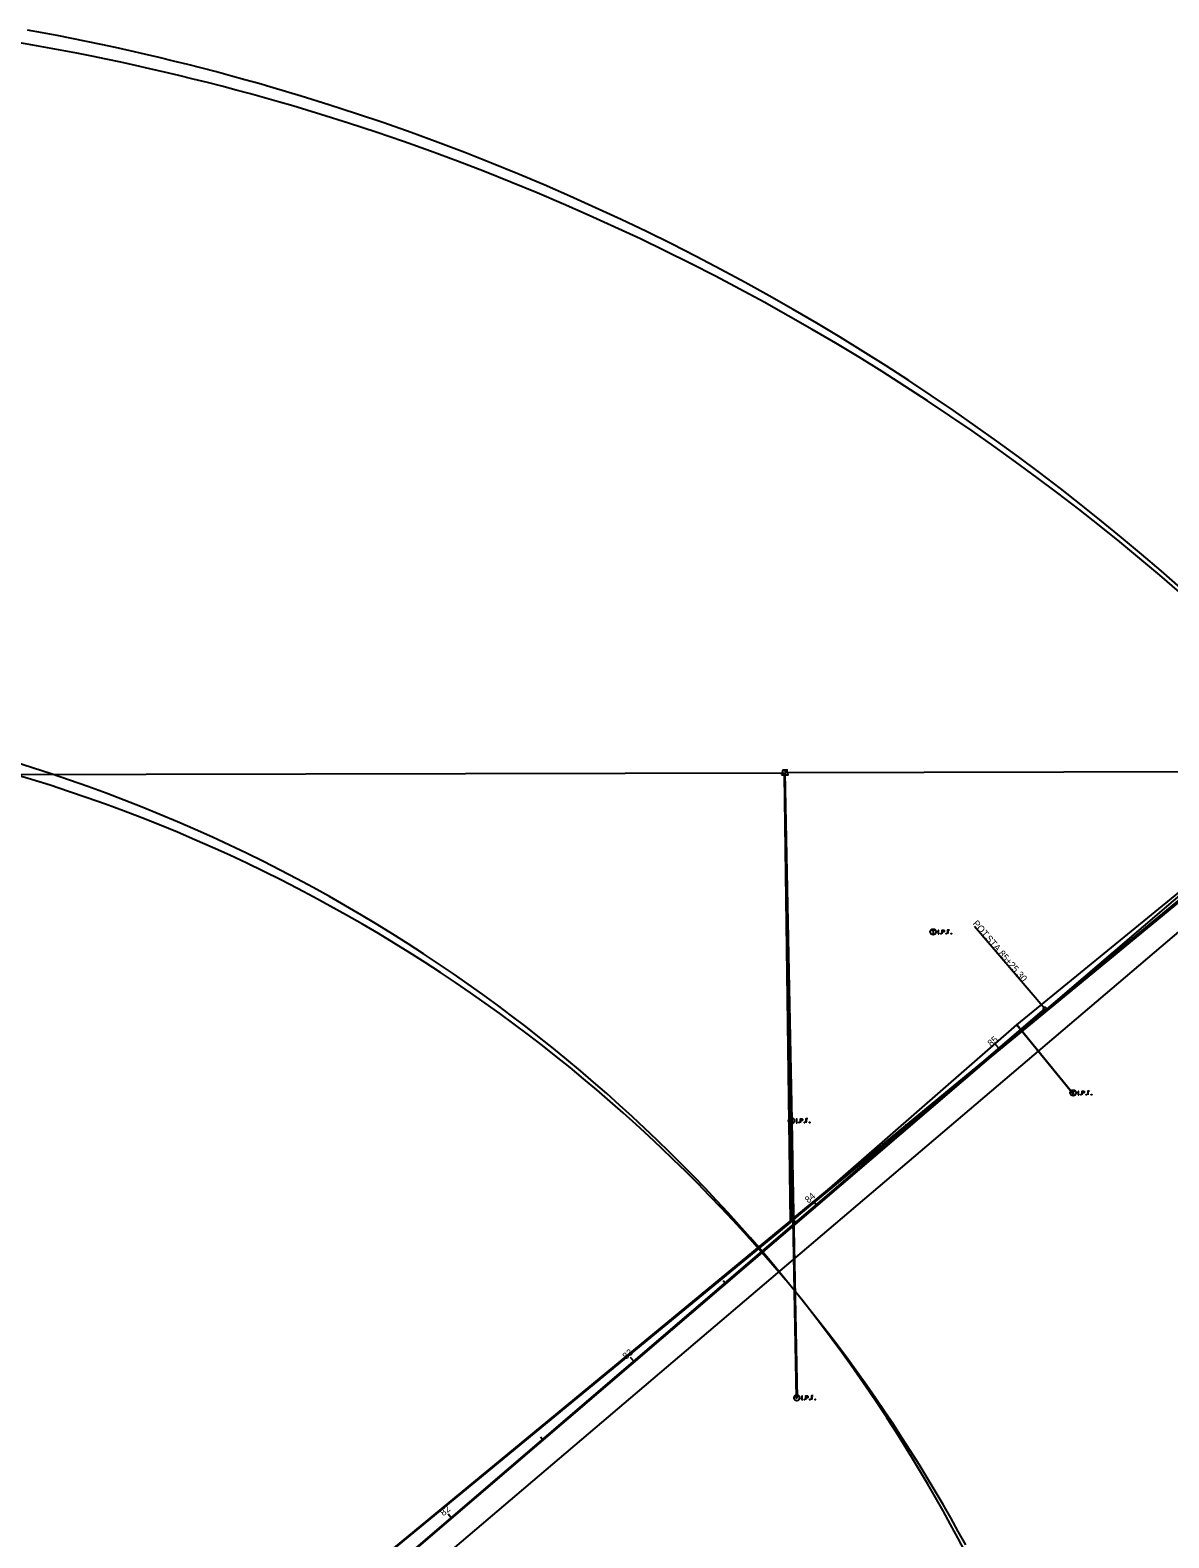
# Model space of a CAD drawing. Extents: x 2180160 to 2188891, y 366108 to 373879.
# Drawn here: x 2185585 to 2186059, y 370801 to 371428 of the extents above; entities that cross this region are included whole.
import ezdxf

# ---------------------------------------------------------------- set-up
doc = ezdxf.new("R2010")
doc.units = 0
for name, color, linetype in [('DR_Pond', 7, 'Continuous'), ('PV_X_Driveway', 7, 'Continuous'), ('RD_X_Concrete_Pad', 7, 'Continuous'), ('RD_X_Gate', 7, 'Continuous'), ('RW_P_Easement_Area', 7, 'Continuous'), ('RW_X_CL', 7, 'Continuous'), ('SC_Scratch1', 7, 'Continuous'), ('SC_Scratch4', 7, 'Continuous'), ('SC_Scratch5', 7, 'Continuous'), ('SC_Scratch6', 7, 'Continuous'), ('SC_Scratch8', 7, 'Continuous'), ('SV_P_Control_Cells_Set', 7, 'Continuous'), ('SV_X_Mon_Cells_Found', 7, 'Continuous'), ('SV_X_Shot_Marker', 7, 'Continuous')]:
    doc.layers.add(name, color=color, linetype=linetype)

msp = doc.modelspace()

# ---------------------------------------------------------------- linework, layer by layer
at = {"layer": 'DR_Pond'}
msp.add_line((2186007.46, 371021.34), (2185978.17, 371055.51), dxfattribs=at)
msp.add_circle((2186007.46, 371021.34), 0.6, dxfattribs=at)
at = {"layer": 'PV_X_Driveway'}
for p, q in [((2185988.25, 371004.87), (2185986.95, 371006.39)), ((2185950.29, 370972.33), (2185949.51, 370973.24)), ((2185912.33, 370939.78), (2185911.03, 370941.3)), ((2185874.37, 370907.24), (2185873.59, 370908.15)), ((2185836.41, 370874.7), (2185835.11, 370876.21)), ((2185798.46, 370842.15), (2185797.68, 370843.06)), ((2185760.5, 370809.61), (2185759.2, 370811.12))]:
    msp.add_line(p, q, dxfattribs=at)
at = {"layer": 'RD_X_Concrete_Pad'}
msp.add_line((2186829.27, 371121.5), (2185899.27, 371119.5), dxfattribs=at)
at = {"layer": 'RD_X_Gate'}
msp.add_line((2185899.28, 371119.5), (2185904.39, 370859.3), dxfattribs=at)
at = {"layer": 'RW_P_Easement_Area'}
msp.add_line((2185124.18, 370293.01), (2185902.93, 370933.53), dxfattribs=at)
at = {"layer": 'RW_X_CL'}
for q in [(2186007.46, 371021.34), (2185902.97, 370931.76)]:
    msp.add_line((2185380.91, 370484.16), q, dxfattribs=at)
at = {"layer": 'SC_Scratch1'}
for points in [[(2184931.61, 370719.54), (2184969.27, 371117.49), (2185899.27, 371119.5)], [(2185899.26, 371119.49), (2185902.12, 370974.78), (2185902.93, 370933.53), (2185124.18, 370293.01)]]:
    msp.add_lwpolyline(points, dxfattribs=at)
at = {"layer": 'SC_Scratch4'}
msp.add_lwpolyline([(2185898.94, 371118.61), (2185901.45, 370932.63), (2186129.11, 371120.01), (2185370.99, 370496.01), (2185380.69, 370483.98), (2185399.53, 370460.63), (2185361.86, 370507.33), (2185271.47, 370460.11), (2185108.08, 370328.3), (2185037.98, 370271.74), (2184997.75, 370213.58), (2184997.03, 370187.86), (2184952.11, 370150.89), (2184977.3, 370119.66), (2184958.46, 370143.01), (2184952.11, 370150.89), (2184426.3, 369718.09)], dxfattribs=at)
at = {"layer": 'SC_Scratch5'}
for p, q in [((2186133.45, 371128.46), (2185384.67, 370487.88)), ((2186140.76, 371119.43), (2185389.97, 370481.23)), ((2185899.28, 371119.5), (2185904.16, 370859.41))]:
    msp.add_line(p, q, dxfattribs=at)
for points in [[(2186063.88, 371196.36), (2186055.81, 371203.42), (2186047.64, 371210.41), (2186039.36, 371217.34), (2186030.98, 371224.2), (2186022.49, 371230.99), (2186013.9, 371237.71), (2186005.2, 371244.36), (2185996.4, 371250.93), (2185987.49, 371257.43), (2185978.48, 371263.85), (2185969.37, 371270.2), (2185960.15, 371276.46), (2185950.83, 371282.64), (2185941.41, 371288.73), (2185931.88, 371294.74), (2185922.26, 371300.65), (2185912.53, 371306.48), (2185902.7, 371312.21), (2185892.78, 371317.85), (2185882.75, 371323.4), (2185872.63, 371328.84), (2185862.41, 371334.18), (2185852.09, 371339.43), (2185841.68, 371344.56), (2185831.17, 371349.59), (2185820.57, 371354.52), (2185809.87, 371359.33), (2185799.09, 371364.03), (2185788.21, 371368.62), (2185777.24, 371373.09), (2185766.18, 371377.44), (2185755.03, 371381.67), (2185743.8, 371385.78), (2185732.48, 371389.77), (2185721.07, 371393.63), (2185709.58, 371397.36), (2185698.01, 371400.97), (2185686.36, 371404.44), (2185680.51, 371406.13), (2185674.63, 371407.78), (2185668.74, 371409.4), (2185662.82, 371410.98), (2185656.89, 371412.53), (2185650.94, 371414.05), (2185644.97, 371415.53), (2185638.98, 371416.98), (2185632.97, 371418.39), (2185626.95, 371419.76), (2185620.91, 371421.1), (2185614.85, 371422.41), (2185608.77, 371423.67), (2185602.67, 371424.9), (2185596.56, 371426.1), (2185590.43, 371427.26), (2185584.28, 371428.38)], [(2186063.36, 371194.64), (2186055.21, 371201.66), (2186046.96, 371208.61), (2186038.6, 371215.5), (2186030.13, 371222.32), (2186021.56, 371229.06), (2186012.88, 371235.74), (2186004.1, 371242.34), (2185995.21, 371248.87), (2185986.22, 371255.32), (2185977.13, 371261.69), (2185967.93, 371267.98), (2185958.63, 371274.19), (2185949.23, 371280.31), (2185939.72, 371286.35), (2185930.12, 371292.3), (2185920.41, 371298.16), (2185910.6, 371303.92), (2185900.69, 371309.59), (2185890.69, 371315.17), (2185880.58, 371320.64), (2185870.38, 371326.02), (2185860.08, 371331.29), (2185849.68, 371336.46), (2185839.19, 371341.53), (2185828.6, 371346.48), (2185817.92, 371351.33), (2185807.15, 371356.06), (2185796.28, 371360.69), (2185785.33, 371365.19), (2185774.28, 371369.58), (2185763.15, 371373.85), (2185751.93, 371377.99), (2185740.62, 371382.01), (2185729.23, 371385.91), (2185717.75, 371389.68), (2185706.19, 371393.32), (2185694.55, 371396.83), (2185688.7, 371398.54), (2185682.83, 371400.21), (2185676.94, 371401.84), (2185671.03, 371403.45), (2185665.11, 371405.02), (2185659.16, 371406.55), (2185653.19, 371408.05), (2185647.21, 371409.52), (2185641.21, 371410.95), (2185635.19, 371412.34), (2185629.15, 371413.7), (2185623.09, 371415.02), (2185617.02, 371416.31), (2185610.93, 371417.56), (2185604.82, 371418.77), (2185598.69, 371419.95), (2185592.55, 371421.09), (2185586.39, 371422.19), (2185580.22, 371423.26)], [(2185974.15, 370795.68), (2185971.2, 370801.27), (2185968.18, 370806.85), (2185965.1, 370812.42), (2185961.96, 370817.99), (2185958.75, 370823.54), (2185955.47, 370829.08), (2185952.12, 370834.62), (2185948.71, 370840.14), (2185945.24, 370845.64), (2185941.69, 370851.14), (2185938.08, 370856.62), (2185934.4, 370862.08), (2185930.65, 370867.53), (2185926.83, 370872.96), (2185922.95, 370878.37), (2185919, 370883.77), (2185914.97, 370889.14), (2185910.88, 370894.49), (2185906.72, 370899.82), (2185902.49, 370905.13), (2185898.18, 370910.41), (2185893.81, 370915.67), (2185889.37, 370920.9), (2185884.86, 370926.11), (2185880.27, 370931.29), (2185875.62, 370936.43), (2185870.89, 370941.55), (2185866.1, 370946.64), (2185861.23, 370951.69), (2185856.29, 370956.71), (2185851.28, 370961.7), (2185846.2, 370966.65), (2185841.05, 370971.56), (2185835.82, 370976.44), (2185830.53, 370981.28), (2185825.16, 370986.07), (2185819.72, 370990.83), (2185814.21, 370995.54), (2185808.63, 371000.21), (2185802.98, 371004.84), (2185797.26, 371009.41), (2185791.47, 371013.95), (2185785.61, 371018.43), (2185779.67, 371022.86), (2185773.67, 371027.24), (2185767.59, 371031.57), (2185761.45, 371035.85), (2185755.24, 371040.07), (2185748.95, 371044.23), (2185742.6, 371048.34), (2185736.18, 371052.39), (2185729.69, 371056.38), (2185723.14, 371060.3), (2185716.51, 371064.17), (2185709.82, 371067.97), (2185703.07, 371071.71), (2185696.24, 371075.38), (2185689.35, 371078.98), (2185682.4, 371082.51), (2185675.38, 371085.98), (2185668.29, 371089.37), (2185661.15, 371092.69), (2185653.94, 371095.93), (2185646.67, 371099.1), (2185639.33, 371102.19), (2185631.94, 371105.2), (2185624.48, 371108.14), (2185616.97, 371110.99), (2185609.39, 371113.76), (2185601.76, 371116.45), (2185594.07, 371119.05), (2185586.33, 371121.57), (2185578.53, 371124)], [(2185974.48, 370798.35), (2185971.42, 370803.93), (2185968.29, 370809.51), (2185965.1, 370815.07), (2185961.84, 370820.63), (2185958.51, 370826.17), (2185955.12, 370831.7), (2185951.66, 370837.22), (2185948.13, 370842.72), (2185944.54, 370848.22), (2185940.87, 370853.69), (2185937.14, 370859.15), (2185933.34, 370864.59), (2185929.48, 370870.02), (2185925.54, 370875.42), (2185921.53, 370880.81), (2185917.46, 370886.18), (2185913.31, 370891.52), (2185909.1, 370896.84), (2185904.81, 370902.14), (2185900.46, 370907.41), (2185896.03, 370912.65), (2185891.53, 370917.87), (2185886.97, 370923.07), (2185882.33, 370928.23), (2185877.62, 370933.36), (2185872.84, 370938.46), (2185867.99, 370943.53), (2185863.06, 370948.57), (2185858.07, 370953.57), (2185853, 370958.54), (2185847.87, 370963.47), (2185842.66, 370968.36), (2185837.38, 370973.22), (2185832.03, 370978.03), (2185826.6, 370982.8), (2185821.11, 370987.53), (2185815.55, 370992.22), (2185809.91, 370996.86), (2185804.2, 371001.46), (2185798.42, 371006.01), (2185792.57, 371010.51), (2185786.65, 371014.96), (2185780.66, 371019.36), (2185774.6, 371023.71), (2185768.47, 371028), (2185762.27, 371032.24), (2185756.01, 371036.43), (2185749.67, 371040.55), (2185743.26, 371044.62), (2185736.78, 371048.63), (2185730.24, 371052.58), (2185723.63, 371056.47), (2185716.95, 371060.29), (2185710.2, 371064.05), (2185703.39, 371067.74), (2185696.51, 371071.36), (2185689.57, 371074.92), (2185682.56, 371078.4), (2185675.49, 371081.82), (2185668.35, 371085.16), (2185661.15, 371088.42), (2185653.89, 371091.62), (2185646.57, 371094.73), (2185639.18, 371097.77), (2185631.73, 371100.73), (2185624.23, 371103.6), (2185616.67, 371106.4), (2185609.04, 371109.11), (2185601.36, 371111.74), (2185593.63, 371114.28), (2185585.84, 371116.73), (2185577.99, 371119.1)], [(2185899.27, 371119.5), (2185902, 370974.67), (2185902.77, 370933.42), (2185904.16, 370859.41), (2185902.77, 370933.42), (2185995.81, 371014.61), (2186019.17, 370986), (2185995.81, 371014.61), (2186127.45, 371122.17)]]:
    msp.add_lwpolyline(points, dxfattribs=at)
at = {"layer": 'SC_Scratch6'}
msp.add_lwpolyline([(2185899.27, 371119.5), (2185901.98, 370933.52), (2186129.44, 371121.15), (2185371.99, 370496.33), (2185381.71, 370484.31), (2185400.57, 370460.98), (2185371.99, 370496.33), (2184953.09, 370150.77), (2184427.75, 369717.42), (2184953.09, 370150.77), (2184959.46, 370142.91), (2184915.13, 370107.07), (2185381.71, 370484.31)], dxfattribs=at)
at = {"layer": 'SC_Scratch8'}
msp.add_lwpolyline([(2185898.94, 371118.61), (2185901.45, 370932.63), (2186129.11, 371120.01), (2185370.99, 370496.01), (2185380.69, 370483.98), (2185399.53, 370460.63), (2185361.86, 370507.33), (2185271.47, 370460.11), (2185108.08, 370328.3), (2185037.98, 370271.74), (2184997.75, 370213.58), (2184997.03, 370187.86), (2184952.11, 370150.89), (2184977.3, 370119.66), (2184958.46, 370143.01), (2184952.11, 370150.89), (2184863.14, 370077.66)], dxfattribs=at)
at = {"layer": 'SV_P_Control_Cells_Set'}
for p, q in [((2185902.27, 370932.86), (2185903.6, 370934.2)), ((2185902.27, 370934.2), (2185903.6, 370932.86))]:
    msp.add_line(p, q, dxfattribs=at)
at = {"layer": 'SV_X_Mon_Cells_Found'}
for p, q in [((2185899.27, 371120.59), (2185899.27, 371119.99)), ((2185960.96, 371053.37), (2185960.96, 371052.49)), ((2186019.21, 370986.41), (2186019.21, 370985.52)), ((2185901.99, 370974.85), (2185901.99, 370973.96))]:
    msp.add_line(p, q, dxfattribs=at)
msp.add_lwpolyline([(2185897.87, 371118.59), (2185900.67, 371118.59), (2185900.07, 371120.59), (2185898.47, 371120.59)], close=True, dxfattribs=at)
for points in [[(2185962.99, 371054.06), (2185963.34, 371054.06)], [(2185962.99, 371052.46), (2185963.34, 371052.46)], [(2185963.17, 371052.46), (2185963.17, 371054.06)], [(2185964.13, 371052.67), (2185964.18, 371052.67), (2185964.22, 371052.65), (2185964.25, 371052.6), (2185964.25, 371052.53), (2185964.22, 371052.48), (2185964.18, 371052.46), (2185964.13, 371052.46), (2185964.09, 371052.48), (2185964.06, 371052.53), (2185964.06, 371052.6), (2185964.09, 371052.65), (2185964.13, 371052.67)], [(2185964.73, 371052.46), (2185964.73, 371054.06), (2185965.26, 371054.06), (2185965.32, 371054.05), (2185965.39, 371054.02), (2185965.43, 371054), (2185965.46, 371053.97), (2185965.51, 371053.91), (2185965.54, 371053.84), (2185965.56, 371053.74), (2185965.56, 371053.59), (2185965.55, 371053.54), (2185965.53, 371053.47), (2185965.48, 371053.38), (2185965.44, 371053.34), (2185965.41, 371053.31), (2185965.35, 371053.29), (2185965.26, 371053.28), (2185964.73, 371053.28)], [(2185966.38, 371052.67), (2185966.43, 371052.67), (2185966.46, 371052.65), (2185966.5, 371052.6), (2185966.5, 371052.53), (2185966.46, 371052.48), (2185966.43, 371052.46), (2185966.38, 371052.46), (2185966.34, 371052.48), (2185966.31, 371052.53), (2185966.31, 371052.6), (2185966.34, 371052.65), (2185966.38, 371052.67)], [(2185967.74, 371054.06), (2185966.98, 371054.06), (2185966.98, 371052.46)], [(2185966.98, 371053.28), (2185967.52, 371053.28)], [(2185968.53, 371052.67), (2185968.58, 371052.67), (2185968.61, 371052.65), (2185968.65, 371052.6), (2185968.65, 371052.53), (2185968.61, 371052.48), (2185968.58, 371052.46), (2185968.53, 371052.46), (2185968.49, 371052.48), (2185968.46, 371052.53), (2185968.46, 371052.6), (2185968.49, 371052.65), (2185968.53, 371052.67)], [(2186021.24, 370987.09), (2186021.59, 370987.09)], [(2186021.42, 370985.49), (2186021.42, 370987.09)], [(2186022.98, 370985.49), (2186022.98, 370987.09), (2186023.51, 370987.09), (2186023.57, 370987.08), (2186023.64, 370987.05), (2186023.68, 370987.03), (2186023.71, 370987), (2186023.75, 370986.94), (2186023.79, 370986.88), (2186023.81, 370986.78), (2186023.81, 370986.62), (2186023.8, 370986.57), (2186023.77, 370986.5), (2186023.73, 370986.41), (2186023.69, 370986.37), (2186023.65, 370986.35), (2186023.6, 370986.32), (2186023.51, 370986.31), (2186022.98, 370986.31)], [(2186025.99, 370987.09), (2186025.23, 370987.09), (2186025.23, 370985.49)], [(2186025.23, 370986.31), (2186025.77, 370986.31)], [(2186021.24, 370985.49), (2186021.59, 370985.49)], [(2186022.37, 370985.7), (2186022.43, 370985.7), (2186022.46, 370985.68), (2186022.5, 370985.63), (2186022.5, 370985.57), (2186022.46, 370985.52), (2186022.43, 370985.49), (2186022.37, 370985.49), (2186022.34, 370985.52), (2186022.31, 370985.57), (2186022.31, 370985.63), (2186022.34, 370985.68), (2186022.37, 370985.7)], [(2186024.62, 370985.7), (2186024.68, 370985.7), (2186024.71, 370985.68), (2186024.74, 370985.63), (2186024.74, 370985.57), (2186024.71, 370985.52), (2186024.68, 370985.49), (2186024.62, 370985.49), (2186024.59, 370985.52), (2186024.56, 370985.57), (2186024.56, 370985.63), (2186024.59, 370985.68), (2186024.62, 370985.7)], [(2186026.77, 370985.7), (2186026.83, 370985.7), (2186026.86, 370985.68), (2186026.89, 370985.63), (2186026.89, 370985.57), (2186026.86, 370985.52), (2186026.83, 370985.49), (2186026.77, 370985.49), (2186026.74, 370985.52), (2186026.71, 370985.57), (2186026.71, 370985.63), (2186026.74, 370985.68), (2186026.77, 370985.7)], [(2185904.02, 370975.53), (2185904.38, 370975.53)], [(2185904.02, 370973.93), (2185904.38, 370973.93)], [(2185904.2, 370973.93), (2185904.2, 370975.53)], [(2185905.16, 370974.14), (2185905.21, 370974.14), (2185905.25, 370974.12), (2185905.28, 370974.07), (2185905.28, 370974.01), (2185905.25, 370973.96), (2185905.21, 370973.93), (2185905.16, 370973.93), (2185905.13, 370973.96), (2185905.09, 370974.01), (2185905.09, 370974.07), (2185905.13, 370974.12), (2185905.16, 370974.14)], [(2185905.77, 370973.93), (2185905.77, 370975.53), (2185906.3, 370975.53), (2185906.35, 370975.52), (2185906.43, 370975.49), (2185906.46, 370975.47), (2185906.49, 370975.44), (2185906.54, 370975.38), (2185906.57, 370975.32), (2185906.59, 370975.21), (2185906.59, 370975.06), (2185906.58, 370975.01), (2185906.56, 370974.94), (2185906.52, 370974.85), (2185906.47, 370974.81), (2185906.44, 370974.79), (2185906.38, 370974.76), (2185906.3, 370974.75), (2185905.77, 370974.75)], [(2185907.41, 370974.14), (2185907.46, 370974.14), (2185907.5, 370974.12), (2185907.53, 370974.07), (2185907.53, 370974.01), (2185907.5, 370973.96), (2185907.46, 370973.93), (2185907.41, 370973.93), (2185907.38, 370973.96), (2185907.34, 370974.01), (2185907.34, 370974.07), (2185907.38, 370974.12), (2185907.41, 370974.14)], [(2185908.78, 370975.53), (2185908.01, 370975.53), (2185908.01, 370973.93)], [(2185908.01, 370974.75), (2185908.55, 370974.75)], [(2185909.56, 370974.14), (2185909.61, 370974.14), (2185909.65, 370974.12), (2185909.68, 370974.07), (2185909.68, 370974.01), (2185909.65, 370973.96), (2185909.61, 370973.93), (2185909.56, 370973.93), (2185909.52, 370973.96), (2185909.49, 370974.01), (2185909.49, 370974.07), (2185909.52, 370974.12), (2185909.56, 370974.14)], [(2185906.31, 370860.27), (2185906.66, 370860.27)], [(2185906.31, 370858.67), (2185906.66, 370858.67)], [(2185906.49, 370858.67), (2185906.49, 370860.27)], [(2185907.44, 370858.89), (2185907.5, 370858.89), (2185907.53, 370858.86), (2185907.57, 370858.81), (2185907.57, 370858.75), (2185907.53, 370858.7), (2185907.5, 370858.67), (2185907.44, 370858.67), (2185907.41, 370858.7), (2185907.38, 370858.75), (2185907.38, 370858.81), (2185907.41, 370858.86), (2185907.44, 370858.89)], [(2185908.05, 370858.67), (2185908.05, 370860.27), (2185908.58, 370860.27), (2185908.63, 370860.26), (2185908.71, 370860.23), (2185908.74, 370860.21), (2185908.78, 370860.18), (2185908.82, 370860.12), (2185908.86, 370860.06), (2185908.88, 370859.96), (2185908.88, 370859.81), (2185908.87, 370859.76), (2185908.84, 370859.68), (2185908.8, 370859.59), (2185908.76, 370859.55), (2185908.72, 370859.53), (2185908.67, 370859.5), (2185908.58, 370859.49), (2185908.05, 370859.49)], [(2185909.69, 370858.89), (2185909.75, 370858.89), (2185909.78, 370858.86), (2185909.81, 370858.81), (2185909.81, 370858.75), (2185909.78, 370858.7), (2185909.75, 370858.67), (2185909.69, 370858.67), (2185909.66, 370858.7), (2185909.63, 370858.75), (2185909.63, 370858.81), (2185909.66, 370858.86), (2185909.69, 370858.89)], [(2185911.06, 370860.27), (2185910.3, 370860.27), (2185910.3, 370858.67)], [(2185910.3, 370859.49), (2185910.84, 370859.49)], [(2185911.84, 370858.89), (2185911.9, 370858.89), (2185911.93, 370858.86), (2185911.96, 370858.81), (2185911.96, 370858.75), (2185911.93, 370858.7), (2185911.9, 370858.67), (2185911.84, 370858.67), (2185911.81, 370858.7), (2185911.78, 370858.75), (2185911.78, 370858.81), (2185911.81, 370858.86), (2185911.84, 370858.89)]]:
    msp.add_lwpolyline(points, dxfattribs=at)
for centre, radius in [((2185960.96, 371053.26), 1.2), ((2185960.96, 371053.91), 0.16), ((2186019.21, 370986.29), 1.2), ((2186019.21, 370986.94), 0.16), ((2185901.99, 370974.73), 1.2), ((2185901.99, 370975.38), 0.16), ((2185904.29, 370859.47), 1.2)]:
    msp.add_circle(centre, radius, dxfattribs=at)
at = {"layer": 'SV_X_Shot_Marker'}
for p, q in [((2185899.49, 371120.51), (2185900.49, 371120.51)), ((2185899.99, 371121.01), (2185899.99, 371120.01)), ((2185899.99, 371120.51), (2185899.99, 371120.51))]:
    msp.add_line(p, q, dxfattribs=at)

# ---------------------------------------------------------------- texts
at = {"layer": 'DR_Pond'}
for s, p in [('POT', (2185977.23, 371056.66)), (' STA. ', (2185981.87, 371051.24)), ('85+25.30', (2185987.94, 371044.17))]:
    msp.add_text(s, height=2.8, rotation=310.60881, dxfattribs=at).set_placement(p)
at = {"layer": 'PV_X_Driveway'}
for s, p in [('85', (2185985.04, 371005.41)), ('84', (2185909.06, 370940.28)), ('83', (2185833.21, 370875.24)), ('82', (2185757.28, 370810.14))]:
    msp.add_text(s, height=2.8, rotation=40.60881, dxfattribs=at).set_placement(p)

doc.saveas('drawing.dxf')
